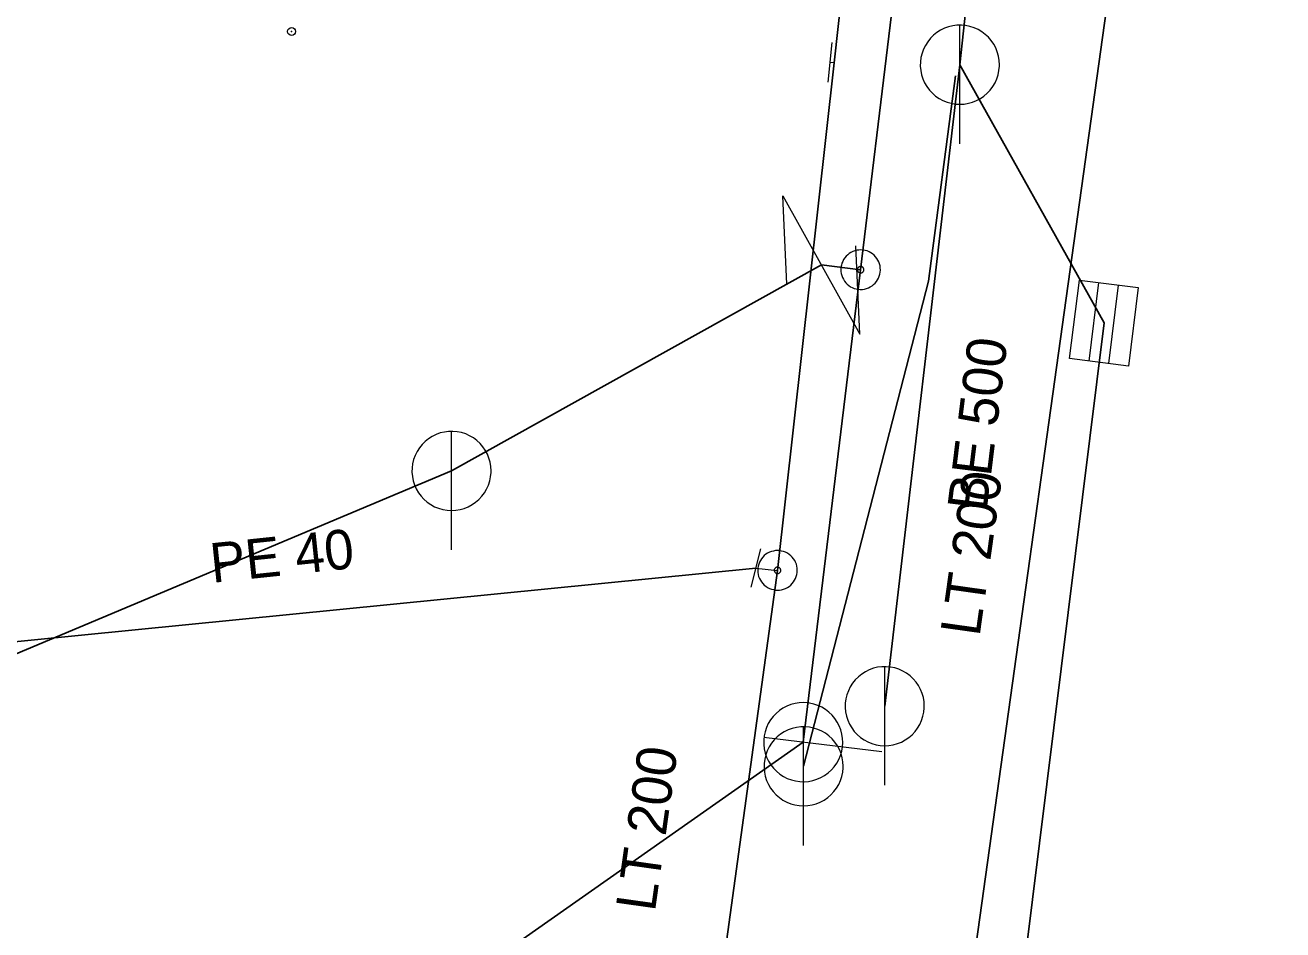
# Model space of a CAD drawing. Extents: x -783064 to -782702, y -1007904 to -1007145.
# Drawn here: x -782836.85 to -782805.07, y -1007723.71 to -1007700.83 of the extents above; entities that cross this region are included whole.
import ezdxf

# ---------------------------------------------------------------- set-up
doc = ezdxf.new("R2010")
doc.units = 0
doc.header["$LTSCALE"] = 0.4
doc.header["$PDMODE"] = 32
doc.header["$PDSIZE"] = 0.2
for name, color, linetype, lineweight in [('1', 7, 'Continuous', 13), ('14', 7, 'Continuous', 13), ('17', 7, 'Continuous', 25), ('22', 7, 'Continuous', 13), ('31', 7, 'Continuous', 13), ('34', 7, 'Continuous', 13), ('47', 7, 'Continuous', 13)]:
    doc.layers.add(name, color=color, linetype=linetype, lineweight=lineweight)

msp = doc.modelspace()

# ---------------------------------------------------------------- linework, layer by layer
at = {"layer": '1'}
msp.add_point((-782830.12, -1007700.989), dxfattribs=at)
at = {"layer": '14', "lineweight": 25}
for p, q in [((-782813.23, -1007701.83), (-782809.579, -1007667.28)), ((-782815.129, -1007718.05), (-782813.23, -1007701.83)), ((-782809.581, -1007708.353), (-782813.23, -1007701.83)), ((-782826.079, -1007712.1), (-782816.73, -1007706.893)), ((-782817.19, -1007718.96), (-782815.738, -1007707.013)), ((-782816.73, -1007706.893), (-782815.738, -1007707.013)), ((-782818.609, -1007780.94), (-782809.581, -1007708.353)), ((-782852.739, -1007723.3), (-782826.079, -1007712.1)), ((-782871.02, -1007756.76), (-782817.19, -1007718.96))]:
    msp.add_line(p, q, dxfattribs=at)
at = {"layer": '14'}
for p, q in [((-782816.41, -1007701.78), (-782816.51, -1007701.77)), ((-782818.39, -1007714.56), (-782817.839, -1007714.615))]:
    msp.add_line(p, q, dxfattribs=at)
at = {"layer": '14', "lineweight": 25}
for points in [[(-782815.738, -1007707.013), (-782814.991, -1007700.828), (-782812.932, -1007683.802), (-782810.82, -1007666.31)], [(-782817.18, -1007719.57), (-782814.026, -1007707.299), (-782813.34, -1007702.11)]]:
    msp.add_lwpolyline(points, dxfattribs=at)
at = {"layer": '17'}
msp.add_line((-782817.839, -1007714.615), (-782819.315, -1007725.369), dxfattribs=at)
for points in [[(-782810.57, -1007649.22), (-782812.17, -1007663.22), (-782814.498, -1007684.393), (-782816.41, -1007701.78), (-782817.839, -1007714.615)], [(-782805.066, -1007668.425), (-782817.623, -1007758.521), (-782825.749, -1007784.698)], [(-782818.39, -1007714.56), (-782840.693, -1007716.775), (-782853.429, -1007722.469), (-782865.128, -1007727.585), (-782866.08, -1007728.001)]]:
    msp.add_lwpolyline(points, dxfattribs=at)
at = {"layer": '22'}
for p, q in [((-782813.23, -1007703.83), (-782813.229, -1007700.83)), ((-782809.96, -1007709.324), (-782809.713, -1007707.339)), ((-782809.464, -1007709.386), (-782809.217, -1007707.401)), ((-782826.079, -1007714.1), (-782826.078, -1007711.1)), ((-782815.129, -1007720.05), (-782815.128, -1007717.05)), ((-782817.18, -1007721.57), (-782817.179, -1007718.57)), ((-782815.204, -1007719.201), (-782818.182, -1007718.839))]:
    msp.add_line(p, q, dxfattribs=at)
for points in [[(-782812.23, -1007701.83), (-782812.235, -1007701.721), (-782812.253, -1007701.613), (-782812.283, -1007701.507), (-782812.323, -1007701.406), (-782812.375, -1007701.309), (-782812.437, -1007701.219), (-782812.509, -1007701.136), (-782812.589, -1007701.062), (-782812.677, -1007700.996), (-782812.771, -1007700.941), (-782812.871, -1007700.896), (-782812.976, -1007700.863), (-782813.083, -1007700.841), (-782813.192, -1007700.831), (-782813.302, -1007700.833), (-782813.41, -1007700.847), (-782813.517, -1007700.872), (-782813.62, -1007700.909), (-782813.718, -1007700.958), (-782813.81, -1007701.016), (-782813.896, -1007701.085), (-782813.973, -1007701.162), (-782814.042, -1007701.248), (-782814.101, -1007701.34), (-782814.149, -1007701.438), (-782814.186, -1007701.541), (-782814.212, -1007701.648), (-782814.226, -1007701.756), (-782814.229, -1007701.866), (-782814.219, -1007701.975), (-782814.198, -1007702.082), (-782814.164, -1007702.186), (-782814.12, -1007702.286), (-782814.065, -1007702.381), (-782813.999, -1007702.469), (-782813.925, -1007702.549), (-782813.842, -1007702.621), (-782813.752, -1007702.683), (-782813.656, -1007702.735), (-782813.554, -1007702.776), (-782813.449, -1007702.806), (-782813.341, -1007702.824), (-782813.231, -1007702.83), (-782813.122, -1007702.824), (-782813.014, -1007702.806), (-782812.909, -1007702.777), (-782812.807, -1007702.736), (-782812.71, -1007702.684), (-782812.62, -1007702.622), (-782812.537, -1007702.551), (-782812.462, -1007702.471), (-782812.397, -1007702.383), (-782812.341, -1007702.289), (-782812.297, -1007702.189), (-782812.263, -1007702.085), (-782812.241, -1007701.977), (-782812.231, -1007701.868)], [(-782810.456, -1007709.262), (-782810.209, -1007707.278), (-782808.721, -1007707.463), (-782808.967, -1007709.448)], [(-782825.079, -1007712.1), (-782825.084, -1007711.991), (-782825.102, -1007711.883), (-782825.132, -1007711.777), (-782825.172, -1007711.676), (-782825.224, -1007711.579), (-782825.286, -1007711.489), (-782825.358, -1007711.406), (-782825.438, -1007711.332), (-782825.526, -1007711.266), (-782825.62, -1007711.211), (-782825.72, -1007711.166), (-782825.825, -1007711.133), (-782825.932, -1007711.111), (-782826.041, -1007711.101), (-782826.151, -1007711.103), (-782826.259, -1007711.117), (-782826.366, -1007711.142), (-782826.469, -1007711.179), (-782826.567, -1007711.228), (-782826.659, -1007711.286), (-782826.745, -1007711.355), (-782826.822, -1007711.432), (-782826.891, -1007711.518), (-782826.95, -1007711.61), (-782826.998, -1007711.708), (-782827.035, -1007711.811), (-782827.061, -1007711.918), (-782827.075, -1007712.026), (-782827.078, -1007712.136), (-782827.068, -1007712.245), (-782827.047, -1007712.352), (-782827.013, -1007712.456), (-782826.969, -1007712.556), (-782826.914, -1007712.651), (-782826.848, -1007712.739), (-782826.774, -1007712.819), (-782826.691, -1007712.891), (-782826.601, -1007712.953), (-782826.505, -1007713.005), (-782826.403, -1007713.046), (-782826.298, -1007713.076), (-782826.19, -1007713.094), (-782826.08, -1007713.1), (-782825.971, -1007713.094), (-782825.863, -1007713.076), (-782825.758, -1007713.047), (-782825.656, -1007713.006), (-782825.559, -1007712.954), (-782825.469, -1007712.892), (-782825.386, -1007712.821), (-782825.311, -1007712.741), (-782825.246, -1007712.653), (-782825.19, -1007712.559), (-782825.146, -1007712.459), (-782825.112, -1007712.355), (-782825.09, -1007712.247), (-782825.08, -1007712.138)], [(-782814.129, -1007718.05), (-782814.134, -1007717.941), (-782814.152, -1007717.833), (-782814.182, -1007717.727), (-782814.222, -1007717.626), (-782814.274, -1007717.529), (-782814.336, -1007717.439), (-782814.408, -1007717.356), (-782814.488, -1007717.282), (-782814.576, -1007717.216), (-782814.67, -1007717.161), (-782814.77, -1007717.116), (-782814.875, -1007717.083), (-782814.982, -1007717.061), (-782815.091, -1007717.051), (-782815.201, -1007717.053), (-782815.309, -1007717.067), (-782815.416, -1007717.092), (-782815.519, -1007717.129), (-782815.617, -1007717.178), (-782815.709, -1007717.236), (-782815.795, -1007717.305), (-782815.872, -1007717.382), (-782815.941, -1007717.468), (-782816, -1007717.56), (-782816.048, -1007717.658), (-782816.085, -1007717.761), (-782816.111, -1007717.868), (-782816.125, -1007717.976), (-782816.128, -1007718.086), (-782816.118, -1007718.195), (-782816.097, -1007718.302), (-782816.063, -1007718.406), (-782816.019, -1007718.506), (-782815.964, -1007718.601), (-782815.898, -1007718.689), (-782815.824, -1007718.769), (-782815.741, -1007718.841), (-782815.651, -1007718.903), (-782815.555, -1007718.955), (-782815.453, -1007718.996), (-782815.348, -1007719.026), (-782815.24, -1007719.044), (-782815.13, -1007719.05), (-782815.021, -1007719.044), (-782814.913, -1007719.026), (-782814.808, -1007718.997), (-782814.706, -1007718.956), (-782814.609, -1007718.904), (-782814.519, -1007718.842), (-782814.436, -1007718.771), (-782814.361, -1007718.691), (-782814.296, -1007718.603), (-782814.24, -1007718.509), (-782814.196, -1007718.409), (-782814.162, -1007718.305), (-782814.14, -1007718.197), (-782814.13, -1007718.088)], [(-782817.068, -1007717.967), (-782817.177, -1007717.96), (-782817.287, -1007717.965), (-782817.396, -1007717.981), (-782817.501, -1007718.009), (-782817.603, -1007718.049), (-782817.7, -1007718.1), (-782817.791, -1007718.161), (-782817.874, -1007718.232), (-782817.95, -1007718.311), (-782818.016, -1007718.398), (-782818.073, -1007718.491), (-782818.118, -1007718.592), (-782818.153, -1007718.695), (-782818.176, -1007718.802), (-782818.188, -1007718.912), (-782818.187, -1007719.021), (-782818.175, -1007719.13), (-782818.15, -1007719.237), (-782818.114, -1007719.34), (-782818.067, -1007719.438), (-782818.009, -1007719.532), (-782817.942, -1007719.618), (-782817.865, -1007719.696), (-782817.781, -1007719.766), (-782817.689, -1007719.826), (-782817.591, -1007719.875), (-782817.488, -1007719.913), (-782817.383, -1007719.94), (-782817.274, -1007719.956), (-782817.164, -1007719.959), (-782817.056, -1007719.951), (-782816.948, -1007719.93), (-782816.844, -1007719.898), (-782816.743, -1007719.855), (-782816.647, -1007719.8), (-782816.559, -1007719.736), (-782816.478, -1007719.663), (-782816.405, -1007719.581), (-782816.342, -1007719.492), (-782816.289, -1007719.395), (-782816.247, -1007719.295), (-782816.216, -1007719.19), (-782816.196, -1007719.081), (-782816.189, -1007718.972), (-782816.194, -1007718.863), (-782816.21, -1007718.755), (-782816.239, -1007718.649), (-782816.279, -1007718.546), (-782816.329, -1007718.45), (-782816.39, -1007718.359), (-782816.46, -1007718.275), (-782816.54, -1007718.199), (-782816.626, -1007718.132), (-782816.72, -1007718.077), (-782816.819, -1007718.03), (-782816.924, -1007717.996), (-782817.031, -1007717.972)], [(-782816.18, -1007719.57), (-782816.185, -1007719.461), (-782816.203, -1007719.353), (-782816.233, -1007719.247), (-782816.273, -1007719.146), (-782816.325, -1007719.049), (-782816.387, -1007718.959), (-782816.459, -1007718.876), (-782816.539, -1007718.802), (-782816.627, -1007718.736), (-782816.721, -1007718.681), (-782816.821, -1007718.636), (-782816.926, -1007718.603), (-782817.033, -1007718.581), (-782817.142, -1007718.571), (-782817.252, -1007718.573), (-782817.36, -1007718.587), (-782817.467, -1007718.612), (-782817.57, -1007718.649), (-782817.668, -1007718.698), (-782817.76, -1007718.756), (-782817.846, -1007718.825), (-782817.923, -1007718.902), (-782817.992, -1007718.988), (-782818.051, -1007719.08), (-782818.099, -1007719.178), (-782818.136, -1007719.281), (-782818.162, -1007719.388), (-782818.176, -1007719.496), (-782818.179, -1007719.606), (-782818.169, -1007719.715), (-782818.148, -1007719.822), (-782818.114, -1007719.926), (-782818.07, -1007720.026), (-782818.015, -1007720.121), (-782817.949, -1007720.209), (-782817.875, -1007720.289), (-782817.792, -1007720.361), (-782817.702, -1007720.423), (-782817.606, -1007720.475), (-782817.504, -1007720.516), (-782817.399, -1007720.546), (-782817.291, -1007720.564), (-782817.181, -1007720.57), (-782817.072, -1007720.564), (-782816.964, -1007720.546), (-782816.859, -1007720.517), (-782816.757, -1007720.476), (-782816.66, -1007720.424), (-782816.57, -1007720.362), (-782816.487, -1007720.291), (-782816.412, -1007720.211), (-782816.347, -1007720.123), (-782816.291, -1007720.029), (-782816.247, -1007719.929), (-782816.213, -1007719.825), (-782816.191, -1007719.717), (-782816.181, -1007719.608)]]:
    msp.add_lwpolyline(points, close=True, dxfattribs=at)
at = {"layer": '31'}
msp.add_lwpolyline([(-782817.603, -1007707.38), (-782817.702, -1007705.146), (-782815.756, -1007708.64), (-782815.856, -1007706.406)], dxfattribs=at)
for points in [[(-782815.677, -1007706.516), (-782815.729, -1007706.513), (-782815.782, -1007706.515), (-782815.833, -1007706.522), (-782815.884, -1007706.534), (-782815.933, -1007706.552), (-782815.981, -1007706.576), (-782816.024, -1007706.604), (-782816.065, -1007706.636), (-782816.103, -1007706.672), (-782816.137, -1007706.712), (-782816.167, -1007706.756), (-782816.19, -1007706.802), (-782816.21, -1007706.85), (-782816.225, -1007706.901), (-782816.234, -1007706.952), (-782816.237, -1007707.004), (-782816.235, -1007707.057), (-782816.228, -1007707.109), (-782816.216, -1007707.159), (-782816.198, -1007707.208), (-782816.174, -1007707.256), (-782816.146, -1007707.3), (-782816.114, -1007707.341), (-782816.078, -1007707.379), (-782816.038, -1007707.412), (-782815.994, -1007707.442), (-782815.948, -1007707.466), (-782815.9, -1007707.485), (-782815.849, -1007707.5), (-782815.798, -1007707.509), (-782815.746, -1007707.512), (-782815.693, -1007707.51), (-782815.641, -1007707.504), (-782815.591, -1007707.491), (-782815.542, -1007707.473), (-782815.495, -1007707.45), (-782815.45, -1007707.422), (-782815.409, -1007707.39), (-782815.371, -1007707.353), (-782815.338, -1007707.313), (-782815.308, -1007707.269), (-782815.284, -1007707.224), (-782815.265, -1007707.175), (-782815.25, -1007707.124), (-782815.241, -1007707.073), (-782815.238, -1007707.021), (-782815.24, -1007706.968), (-782815.246, -1007706.917), (-782815.259, -1007706.866), (-782815.277, -1007706.817), (-782815.3, -1007706.77), (-782815.328, -1007706.726), (-782815.36, -1007706.685), (-782815.397, -1007706.647), (-782815.437, -1007706.613), (-782815.481, -1007706.583), (-782815.526, -1007706.56), (-782815.575, -1007706.54), (-782815.626, -1007706.525)], [(-782815.728, -1007706.931), (-782815.737, -1007706.93), (-782815.745, -1007706.931), (-782815.753, -1007706.932), (-782815.761, -1007706.934), (-782815.77, -1007706.937), (-782815.777, -1007706.941), (-782815.785, -1007706.945), (-782815.791, -1007706.951), (-782815.797, -1007706.957), (-782815.803, -1007706.963), (-782815.808, -1007706.971), (-782815.812, -1007706.978), (-782815.815, -1007706.986), (-782815.818, -1007706.994), (-782815.819, -1007707.003), (-782815.82, -1007707.012), (-782815.819, -1007707.02), (-782815.818, -1007707.028), (-782815.816, -1007707.036), (-782815.813, -1007707.045), (-782815.809, -1007707.052), (-782815.805, -1007707.06), (-782815.799, -1007707.066), (-782815.793, -1007707.073), (-782815.787, -1007707.078), (-782815.779, -1007707.083), (-782815.772, -1007707.087), (-782815.764, -1007707.09), (-782815.756, -1007707.093), (-782815.747, -1007707.094), (-782815.738, -1007707.095), (-782815.73, -1007707.094), (-782815.722, -1007707.093), (-782815.714, -1007707.091), (-782815.705, -1007707.088), (-782815.698, -1007707.085), (-782815.69, -1007707.08), (-782815.684, -1007707.074), (-782815.677, -1007707.068), (-782815.672, -1007707.062), (-782815.667, -1007707.054), (-782815.663, -1007707.047), (-782815.66, -1007707.039), (-782815.657, -1007707.031), (-782815.656, -1007707.022), (-782815.655, -1007707.013), (-782815.656, -1007707.005), (-782815.657, -1007706.997), (-782815.659, -1007706.989), (-782815.662, -1007706.98), (-782815.665, -1007706.973), (-782815.67, -1007706.965), (-782815.676, -1007706.959), (-782815.682, -1007706.953), (-782815.688, -1007706.947), (-782815.696, -1007706.942), (-782815.703, -1007706.938), (-782815.711, -1007706.935), (-782815.719, -1007706.932)]]:
    msp.add_lwpolyline(points, close=True, dxfattribs=at)
at = {"layer": '34'}
for p, q in [((-782816.559, -1007702.267), (-782816.459, -1007701.272)), ((-782818.268, -1007714.074), (-782818.511, -1007715.044))]:
    msp.add_line(p, q, dxfattribs=at)
at = {"layer": '47'}
for points in [[(-782817.785, -1007714.117), (-782817.837, -1007714.115), (-782817.89, -1007714.117), (-782817.941, -1007714.126), (-782817.992, -1007714.138), (-782818.041, -1007714.157), (-782818.088, -1007714.181), (-782818.131, -1007714.21), (-782818.172, -1007714.243), (-782818.209, -1007714.279), (-782818.242, -1007714.32), (-782818.271, -1007714.364), (-782818.294, -1007714.411), (-782818.314, -1007714.459), (-782818.327, -1007714.51), (-782818.336, -1007714.561), (-782818.338, -1007714.613), (-782818.336, -1007714.666), (-782818.327, -1007714.718), (-782818.315, -1007714.768), (-782818.296, -1007714.817), (-782818.272, -1007714.864), (-782818.243, -1007714.908), (-782818.21, -1007714.949), (-782818.174, -1007714.986), (-782818.133, -1007715.018), (-782818.089, -1007715.047), (-782818.042, -1007715.071), (-782817.994, -1007715.09), (-782817.943, -1007715.103), (-782817.892, -1007715.112), (-782817.84, -1007715.114), (-782817.787, -1007715.112), (-782817.735, -1007715.104), (-782817.685, -1007715.091), (-782817.636, -1007715.072), (-782817.589, -1007715.049), (-782817.545, -1007715.02), (-782817.504, -1007714.987), (-782817.467, -1007714.95), (-782817.435, -1007714.909), (-782817.406, -1007714.865), (-782817.382, -1007714.819), (-782817.363, -1007714.77), (-782817.35, -1007714.719), (-782817.341, -1007714.668), (-782817.339, -1007714.616), (-782817.341, -1007714.563), (-782817.349, -1007714.512), (-782817.362, -1007714.461), (-782817.381, -1007714.412), (-782817.404, -1007714.365), (-782817.433, -1007714.322), (-782817.466, -1007714.281), (-782817.503, -1007714.244), (-782817.544, -1007714.211), (-782817.588, -1007714.182), (-782817.634, -1007714.159), (-782817.683, -1007714.139), (-782817.734, -1007714.126)], [(-782817.83, -1007714.533), (-782817.839, -1007714.532), (-782817.847, -1007714.533), (-782817.855, -1007714.534), (-782817.863, -1007714.536), (-782817.872, -1007714.54), (-782817.879, -1007714.544), (-782817.887, -1007714.548), (-782817.893, -1007714.553), (-782817.899, -1007714.56), (-782817.905, -1007714.566), (-782817.91, -1007714.574), (-782817.913, -1007714.581), (-782817.916, -1007714.589), (-782817.919, -1007714.597), (-782817.92, -1007714.606), (-782817.921, -1007714.615), (-782817.92, -1007714.623), (-782817.919, -1007714.631), (-782817.917, -1007714.639), (-782817.913, -1007714.648), (-782817.909, -1007714.655), (-782817.905, -1007714.663), (-782817.9, -1007714.669), (-782817.893, -1007714.676), (-782817.887, -1007714.681), (-782817.879, -1007714.686), (-782817.872, -1007714.689), (-782817.864, -1007714.692), (-782817.856, -1007714.695), (-782817.847, -1007714.696), (-782817.838, -1007714.697), (-782817.83, -1007714.696), (-782817.822, -1007714.695), (-782817.814, -1007714.693), (-782817.805, -1007714.689), (-782817.798, -1007714.686), (-782817.79, -1007714.681), (-782817.784, -1007714.676), (-782817.777, -1007714.669), (-782817.772, -1007714.663), (-782817.767, -1007714.655), (-782817.764, -1007714.648), (-782817.761, -1007714.64), (-782817.758, -1007714.632), (-782817.757, -1007714.623), (-782817.756, -1007714.614), (-782817.757, -1007714.606), (-782817.758, -1007714.598), (-782817.76, -1007714.59), (-782817.764, -1007714.581), (-782817.767, -1007714.574), (-782817.772, -1007714.566), (-782817.777, -1007714.56), (-782817.784, -1007714.554), (-782817.79, -1007714.548), (-782817.798, -1007714.543), (-782817.805, -1007714.54), (-782817.813, -1007714.537), (-782817.821, -1007714.534)]]:
    msp.add_lwpolyline(points, close=True, dxfattribs=at)

# ---------------------------------------------------------------- texts
at = {"layer": '1'}
for s, rotation, p in [('BE 500', 83, (-782812.556, -1007713.149)), ('LT 200', 82, (-782812.733, -1007716.308)), ('PE 40 ', 6, (-782832.126, -1007714.933)), ('LT 200', 82, (-782820.938, -1007723.268))]:
    msp.add_text(s, height=1, rotation=rotation, dxfattribs=at).set_placement(p)

doc.saveas('drawing.dxf')
